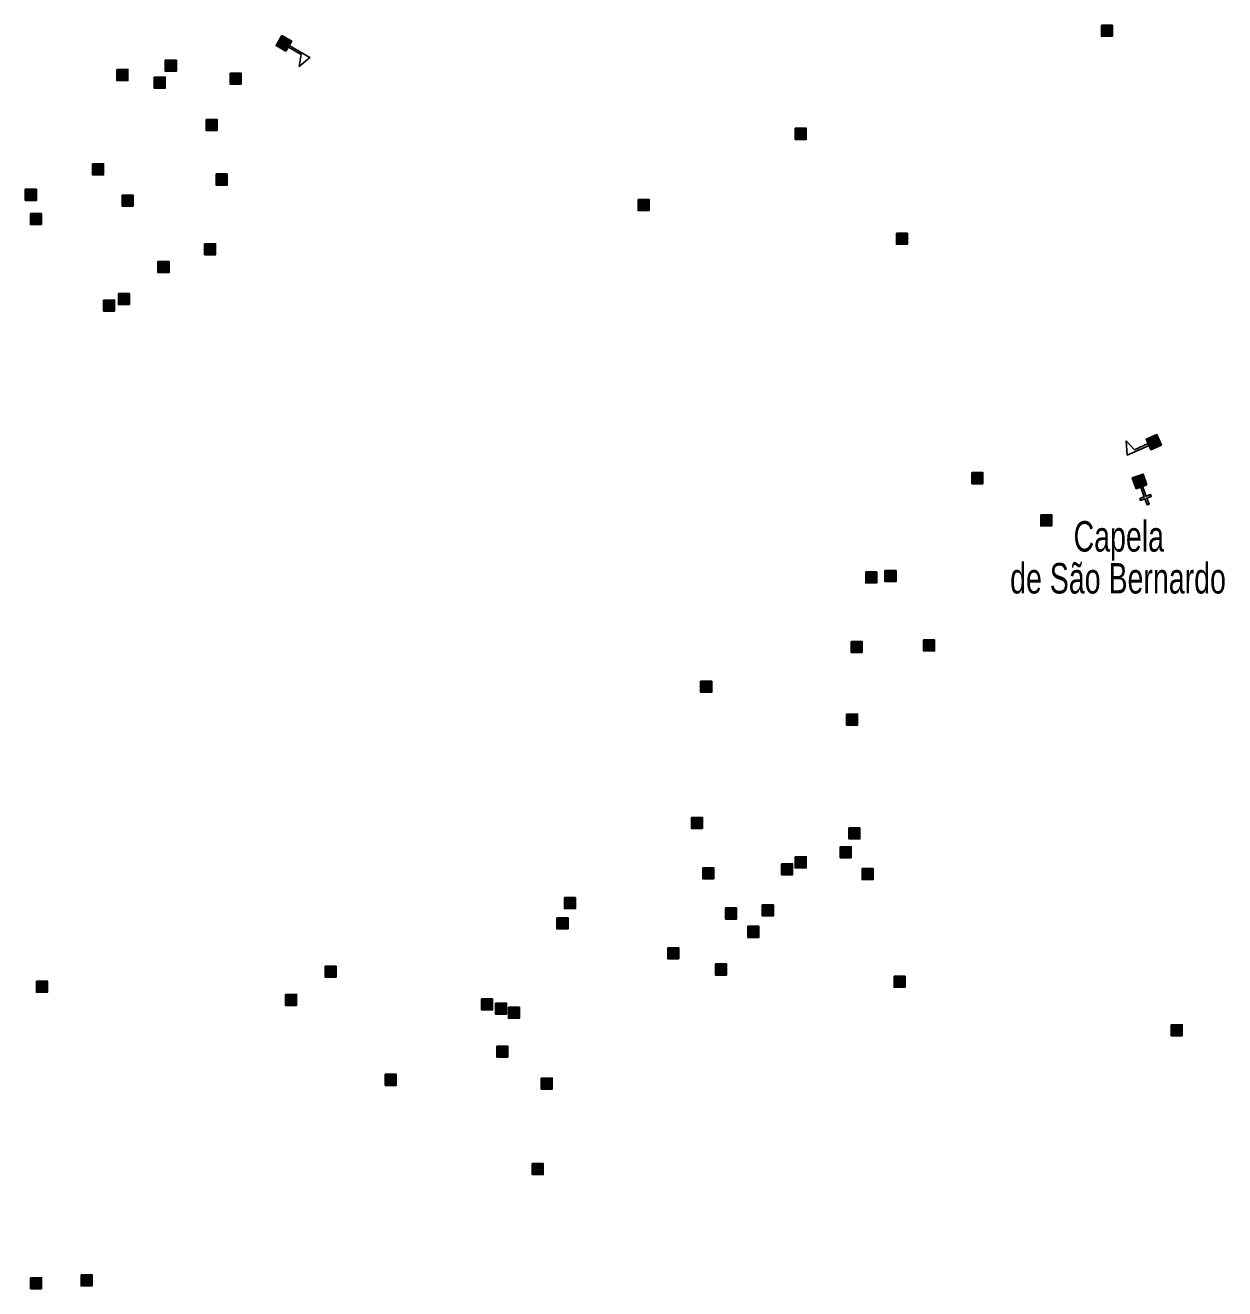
# Model space of a CAD drawing. Extents: x 649.2 to 674.4, y 7040 to 7068.1.
# Drawn here: x 665.009 to 668.156, y 7040.178 to 7043.494 of the extents above; entities that cross this region are included whole.
import ezdxf

# ---------------------------------------------------------------- set-up
doc = ezdxf.new("R2010")
doc.units = 0
doc.header["$LTSCALE"] = 0.032
for name, color, linetype, lineweight in [('2', 7, 'Continuous', 25), ('4', 7, 'Continuous', 25), ('6', 7, 'Continuous', 25)]:
    doc.layers.add(name, color=color, linetype=linetype, lineweight=lineweight)
doc.layers.add('61', color=7, linetype='Continuous')

msp = doc.modelspace()

# ---------------------------------------------------------------- hatches: boundary and pattern name
at = {"layer": '2'}
for points in [[(667.8328, 7043.4944), (667.8618, 7043.4944), (667.8618, 7043.4654), (667.8328, 7043.4654)], [(665.3767, 7043.4025), (665.4057, 7043.4025), (665.4057, 7043.3735), (665.3767, 7043.3735)], [(665.2498, 7043.3783), (665.2788, 7043.3783), (665.2788, 7043.3493), (665.2498, 7043.3493)], [(665.5467, 7043.3689), (665.5757, 7043.3689), (665.5757, 7043.3399), (665.5467, 7043.3399)], [(665.3474, 7043.3584), (665.3764, 7043.3584), (665.3764, 7043.3294), (665.3474, 7043.3294)], [(665.4837, 7043.2472), (665.5127, 7043.2472), (665.5127, 7043.2182), (665.4837, 7043.2182)], [(667.0295, 7043.2239), (667.0585, 7043.2239), (667.0585, 7043.1949), (667.0295, 7043.1949)], [(665.1858, 7043.1307), (665.2148, 7043.1307), (665.2148, 7043.1017), (665.1858, 7043.1017)], [(665.51, 7043.1041), (665.539, 7043.1041), (665.539, 7043.0751), (665.51, 7043.0751)], [(665.0093, 7043.0638), (665.0383, 7043.0638), (665.0383, 7043.0348), (665.0093, 7043.0348)], [(665.2633, 7043.0487), (665.2923, 7043.0487), (665.2923, 7043.0197), (665.2633, 7043.0197)], [(666.617, 7043.0371), (666.646, 7043.0371), (666.646, 7043.0081), (666.617, 7043.0081)], [(665.0226, 7043.0001), (665.0516, 7043.0001), (665.0516, 7042.9711), (665.0226, 7042.9711)], [(667.295, 7042.9484), (667.324, 7042.9484), (667.324, 7042.9194), (667.295, 7042.9194)], [(665.4796, 7042.9211), (665.5086, 7042.9211), (665.5086, 7042.8921), (665.4796, 7042.8921)], [(665.3574, 7042.8741), (665.3864, 7042.8741), (665.3864, 7042.8451), (665.3574, 7042.8451)], [(665.2146, 7042.773), (665.2436, 7042.773), (665.2436, 7042.744), (665.2146, 7042.744)], [(665.2536, 7042.7901), (665.2826, 7042.7901), (665.2826, 7042.7611), (665.2536, 7042.7611)], [(667.493, 7042.3201), (667.522, 7042.3201), (667.522, 7042.2911), (667.493, 7042.2911)], [(667.6736, 7042.2093), (667.7026, 7042.2093), (667.7026, 7042.1803), (667.6736, 7042.1803)], [(667.2144, 7042.0596), (667.2434, 7042.0596), (667.2434, 7042.0306), (667.2144, 7042.0306)], [(667.265, 7042.063), (667.294, 7042.063), (667.294, 7042.034), (667.265, 7042.034)], [(667.1761, 7041.877), (667.2051, 7041.877), (667.2051, 7041.848), (667.1761, 7041.848)], [(667.3662, 7041.8811), (667.3952, 7041.8811), (667.3952, 7041.8521), (667.3662, 7041.8521)], [(666.7813, 7041.7724), (666.8103, 7041.7724), (666.8103, 7041.7434), (666.7813, 7041.7434)], [(667.1641, 7041.6862), (667.1931, 7041.6862), (667.1931, 7041.6572), (667.1641, 7041.6572)], [(666.7571, 7041.415), (666.7861, 7041.415), (666.7861, 7041.386), (666.7571, 7041.386)], [(667.1704, 7041.3874), (667.1994, 7041.3874), (667.1994, 7041.3584), (667.1704, 7041.3584)], [(667.0292, 7041.3116), (667.0582, 7041.3116), (667.0582, 7041.2826), (667.0292, 7041.2826)], [(667.1474, 7041.338), (667.1764, 7041.338), (667.1764, 7041.309), (667.1474, 7041.309)], [(666.7869, 7041.2829), (666.8159, 7041.2829), (666.8159, 7041.2539), (666.7869, 7041.2539)], [(666.9936, 7041.2933), (667.0226, 7041.2933), (667.0226, 7041.2643), (666.9936, 7041.2643)], [(667.2049, 7041.2806), (667.2339, 7041.2806), (667.2339, 7041.2516), (667.2049, 7041.2516)], [(666.4238, 7041.2045), (666.4528, 7041.2045), (666.4528, 7041.1755), (666.4238, 7041.1755)], [(666.8466, 7041.1773), (666.8756, 7041.1773), (666.8756, 7041.1483), (666.8466, 7041.1483)], [(666.9431, 7041.1853), (666.9721, 7041.1853), (666.9721, 7041.1563), (666.9431, 7041.1563)], [(666.4043, 7041.1511), (666.4333, 7041.1511), (666.4333, 7041.1221), (666.4043, 7041.1221)], [(666.9052, 7041.1291), (666.9342, 7041.1291), (666.9342, 7041.1001), (666.9052, 7041.1001)], [(666.695, 7041.0728), (666.724, 7041.0728), (666.724, 7041.0438), (666.695, 7041.0438)], [(665.7959, 7041.0248), (665.8249, 7041.0248), (665.8249, 7040.9958), (665.7959, 7040.9958)], [(666.8202, 7041.0303), (666.8492, 7041.0303), (666.8492, 7041.0013), (666.8202, 7041.0013)], [(665.0384, 7040.9852), (665.0674, 7040.9852), (665.0674, 7040.9562), (665.0384, 7040.9562)], [(667.2887, 7040.9982), (667.3177, 7040.9982), (667.3177, 7040.9692), (667.2887, 7040.9692)], [(665.6922, 7040.9503), (665.7212, 7040.9503), (665.7212, 7040.9213), (665.6922, 7040.9213)], [(666.2064, 7040.9385), (666.2354, 7040.9385), (666.2354, 7040.9095), (666.2064, 7040.9095)], [(666.2428, 7040.9276), (666.2718, 7040.9276), (666.2718, 7040.8986), (666.2428, 7040.8986)], [(666.2768, 7040.9167), (666.3058, 7040.9167), (666.3058, 7040.8877), (666.2768, 7040.8877)], [(668.0158, 7040.8708), (668.0448, 7040.8708), (668.0448, 7040.8418), (668.0158, 7040.8418)], [(666.2464, 7040.8147), (666.2754, 7040.8147), (666.2754, 7040.7857), (666.2464, 7040.7857)], [(665.9538, 7040.7406), (665.9828, 7040.7406), (665.9828, 7040.7116), (665.9538, 7040.7116)], [(666.363, 7040.7309), (666.392, 7040.7309), (666.392, 7040.7019), (666.363, 7040.7019)], [(666.3395, 7040.5064), (666.3685, 7040.5064), (666.3685, 7040.4774), (666.3395, 7040.4774)], [(665.1555, 7040.2143), (665.1845, 7040.2143), (665.1845, 7040.1853), (665.1555, 7040.1853)], [(665.0231, 7040.2068), (665.0521, 7040.2068), (665.0521, 7040.1778), (665.0231, 7040.1778)]]:
    msp.add_hatch(color=256, dxfattribs=at).paths.add_polyline_path(points)
at = {"layer": '4'}
for points in [[(665.6825, 7043.4675), (665.7083, 7043.4524), (665.6932, 7043.4265), (665.6674, 7043.4417)], [(667.9902, 7042.3924), (667.9628, 7042.3803), (667.9506, 7042.4077), (667.978, 7042.4199)]]:
    msp.add_hatch(color=256, dxfattribs=at).paths.add_polyline_path(points)
at = {"layer": '6'}
for points in [[(667.9524, 7042.2882), (667.942, 7042.3163), (667.9139, 7042.306), (667.9242, 7042.2778)], [(667.9359, 7042.2821), (667.9406, 7042.2839), (667.9501, 7042.258), (667.9618, 7042.2624), (667.9636, 7042.2577), (667.9518, 7042.2534), (667.9579, 7042.2369), (667.9532, 7042.2352), (667.9471, 7042.2516), (667.9354, 7042.2473), (667.9337, 7042.252), (667.9454, 7042.2563)]]:
    msp.add_hatch(color=256, dxfattribs=at).paths.add_polyline_path(points)

# ---------------------------------------------------------------- linework, layer by layer
at = {"layer": '2'}
for points in [[(667.8328, 7043.4944), (667.8618, 7043.4944), (667.8618, 7043.4654), (667.8328, 7043.4654)], [(665.3767, 7043.4025), (665.4057, 7043.4025), (665.4057, 7043.3735), (665.3767, 7043.3735)], [(665.2498, 7043.3783), (665.2788, 7043.3783), (665.2788, 7043.3493), (665.2498, 7043.3493)], [(665.5467, 7043.3689), (665.5757, 7043.3689), (665.5757, 7043.3399), (665.5467, 7043.3399)], [(665.3474, 7043.3584), (665.3764, 7043.3584), (665.3764, 7043.3294), (665.3474, 7043.3294)], [(665.4837, 7043.2472), (665.5127, 7043.2472), (665.5127, 7043.2182), (665.4837, 7043.2182)], [(667.0295, 7043.2239), (667.0585, 7043.2239), (667.0585, 7043.1949), (667.0295, 7043.1949)], [(665.1858, 7043.1307), (665.2148, 7043.1307), (665.2148, 7043.1017), (665.1858, 7043.1017)], [(665.51, 7043.1041), (665.539, 7043.1041), (665.539, 7043.0751), (665.51, 7043.0751)], [(665.0093, 7043.0638), (665.0383, 7043.0638), (665.0383, 7043.0348), (665.0093, 7043.0348)], [(665.2633, 7043.0487), (665.2923, 7043.0487), (665.2923, 7043.0197), (665.2633, 7043.0197)], [(666.617, 7043.0371), (666.646, 7043.0371), (666.646, 7043.0081), (666.617, 7043.0081)], [(665.0226, 7043.0001), (665.0516, 7043.0001), (665.0516, 7042.9711), (665.0226, 7042.9711)], [(667.295, 7042.9484), (667.324, 7042.9484), (667.324, 7042.9194), (667.295, 7042.9194)], [(665.4796, 7042.9211), (665.5086, 7042.9211), (665.5086, 7042.8921), (665.4796, 7042.8921)], [(665.3574, 7042.8741), (665.3864, 7042.8741), (665.3864, 7042.8451), (665.3574, 7042.8451)], [(665.2146, 7042.773), (665.2436, 7042.773), (665.2436, 7042.744), (665.2146, 7042.744)], [(665.2536, 7042.7901), (665.2826, 7042.7901), (665.2826, 7042.7611), (665.2536, 7042.7611)], [(667.493, 7042.3201), (667.522, 7042.3201), (667.522, 7042.2911), (667.493, 7042.2911)], [(667.6736, 7042.2093), (667.7026, 7042.2093), (667.7026, 7042.1803), (667.6736, 7042.1803)], [(667.2144, 7042.0596), (667.2434, 7042.0596), (667.2434, 7042.0306), (667.2144, 7042.0306)], [(667.265, 7042.063), (667.294, 7042.063), (667.294, 7042.034), (667.265, 7042.034)], [(667.1761, 7041.877), (667.2051, 7041.877), (667.2051, 7041.848), (667.1761, 7041.848)], [(667.3662, 7041.8811), (667.3952, 7041.8811), (667.3952, 7041.8521), (667.3662, 7041.8521)], [(666.7813, 7041.7724), (666.8103, 7041.7724), (666.8103, 7041.7434), (666.7813, 7041.7434)], [(667.1641, 7041.6862), (667.1931, 7041.6862), (667.1931, 7041.6572), (667.1641, 7041.6572)], [(666.7571, 7041.415), (666.7861, 7041.415), (666.7861, 7041.386), (666.7571, 7041.386)], [(667.1704, 7041.3874), (667.1994, 7041.3874), (667.1994, 7041.3584), (667.1704, 7041.3584)], [(667.0292, 7041.3116), (667.0582, 7041.3116), (667.0582, 7041.2826), (667.0292, 7041.2826)], [(667.1474, 7041.338), (667.1764, 7041.338), (667.1764, 7041.309), (667.1474, 7041.309)], [(666.7869, 7041.2829), (666.8159, 7041.2829), (666.8159, 7041.2539), (666.7869, 7041.2539)], [(666.9936, 7041.2933), (667.0226, 7041.2933), (667.0226, 7041.2643), (666.9936, 7041.2643)], [(667.2049, 7041.2806), (667.2339, 7041.2806), (667.2339, 7041.2516), (667.2049, 7041.2516)], [(666.4238, 7041.2045), (666.4528, 7041.2045), (666.4528, 7041.1755), (666.4238, 7041.1755)], [(666.8466, 7041.1773), (666.8756, 7041.1773), (666.8756, 7041.1483), (666.8466, 7041.1483)], [(666.9431, 7041.1853), (666.9721, 7041.1853), (666.9721, 7041.1563), (666.9431, 7041.1563)], [(666.4043, 7041.1511), (666.4333, 7041.1511), (666.4333, 7041.1221), (666.4043, 7041.1221)], [(666.9052, 7041.1291), (666.9342, 7041.1291), (666.9342, 7041.1001), (666.9052, 7041.1001)], [(666.695, 7041.0728), (666.724, 7041.0728), (666.724, 7041.0438), (666.695, 7041.0438)], [(665.7959, 7041.0248), (665.8249, 7041.0248), (665.8249, 7040.9958), (665.7959, 7040.9958)], [(666.8202, 7041.0303), (666.8492, 7041.0303), (666.8492, 7041.0013), (666.8202, 7041.0013)], [(665.0384, 7040.9852), (665.0674, 7040.9852), (665.0674, 7040.9562), (665.0384, 7040.9562)], [(667.2887, 7040.9982), (667.3177, 7040.9982), (667.3177, 7040.9692), (667.2887, 7040.9692)], [(665.6922, 7040.9503), (665.7212, 7040.9503), (665.7212, 7040.9213), (665.6922, 7040.9213)], [(666.2064, 7040.9385), (666.2354, 7040.9385), (666.2354, 7040.9095), (666.2064, 7040.9095)], [(666.2428, 7040.9276), (666.2718, 7040.9276), (666.2718, 7040.8986), (666.2428, 7040.8986)], [(666.2768, 7040.9167), (666.3058, 7040.9167), (666.3058, 7040.8877), (666.2768, 7040.8877)], [(668.0158, 7040.8708), (668.0448, 7040.8708), (668.0448, 7040.8418), (668.0158, 7040.8418)], [(666.2464, 7040.8147), (666.2754, 7040.8147), (666.2754, 7040.7857), (666.2464, 7040.7857)], [(665.9538, 7040.7406), (665.9828, 7040.7406), (665.9828, 7040.7116), (665.9538, 7040.7116)], [(666.363, 7040.7309), (666.392, 7040.7309), (666.392, 7040.7019), (666.363, 7040.7019)], [(666.3395, 7040.5064), (666.3685, 7040.5064), (666.3685, 7040.4774), (666.3395, 7040.4774)], [(665.1555, 7040.2143), (665.1845, 7040.2143), (665.1845, 7040.1853), (665.1555, 7040.1853)], [(665.0231, 7040.2068), (665.0521, 7040.2068), (665.0521, 7040.1778), (665.0231, 7040.1778)]]:
    msp.add_lwpolyline(points, close=True, dxfattribs=at)
at = {"layer": '4'}
for p, q in [((665.7021, 7043.4416), (665.6995, 7043.4373)), ((667.9577, 7042.3917), (667.9557, 7042.3963))]:
    msp.add_line(p, q, dxfattribs=at)
for points in [[(665.6825, 7043.4675), (665.7083, 7043.4524), (665.6932, 7043.4265), (665.6674, 7043.4417)], [(665.7021, 7043.4416), (665.756, 7043.4101), (665.7276, 7043.3862), (665.7336, 7043.4174), (665.6995, 7043.4373)], [(667.9577, 7042.3917), (667.9006, 7042.3663), (667.8978, 7042.4034), (667.9196, 7042.3802), (667.9557, 7042.3963)], [(667.9902, 7042.3924), (667.9628, 7042.3803), (667.9506, 7042.4077), (667.978, 7042.4199)]]:
    msp.add_lwpolyline(points, close=True, dxfattribs=at)
at = {"layer": '6'}
for points in [[(667.9524, 7042.2882), (667.942, 7042.3163), (667.9139, 7042.306), (667.9242, 7042.2778)], [(667.9359, 7042.2821), (667.9406, 7042.2839), (667.9501, 7042.258), (667.9618, 7042.2624), (667.9636, 7042.2577), (667.9518, 7042.2534), (667.9579, 7042.2369), (667.9532, 7042.2352), (667.9471, 7042.2516), (667.9354, 7042.2473), (667.9337, 7042.252), (667.9454, 7042.2563)]]:
    msp.add_lwpolyline(points, close=True, dxfattribs=at)

# ---------------------------------------------------------------- texts
at = {"layer": '61', "width": 0.7}
for s, p in [('        Capela  ', (667.5933, 7042.1128)), ('de São Bernardo', (667.5933, 7042.0028))]:
    msp.add_text(s, height=0.08, dxfattribs=at).set_placement(p)

doc.saveas('drawing.dxf')
